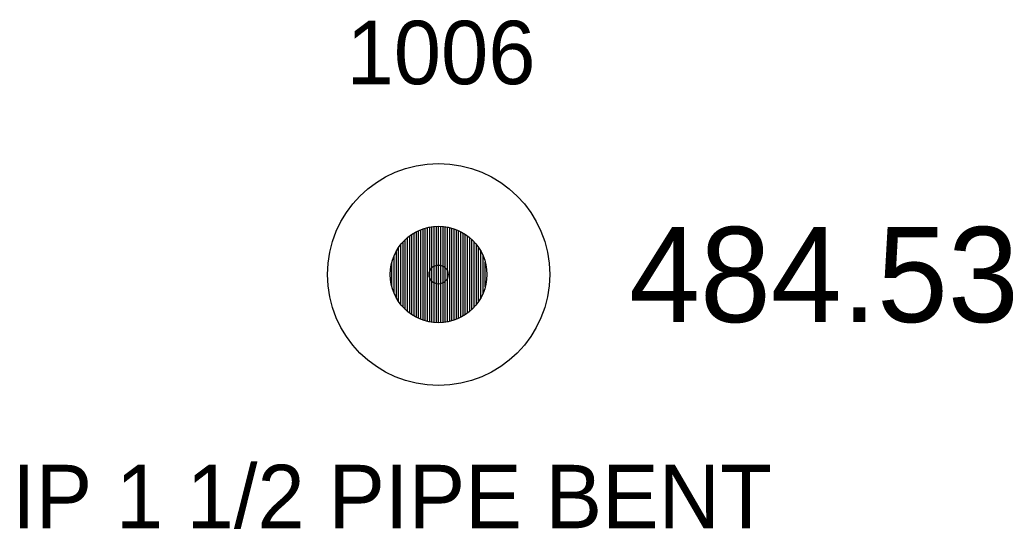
# Model space of a CAD drawing. Extents: x 1796360 to 1799195, y 895805 to 899730.
# Drawn here: x 1799179.36 to 1799195, y 899593.12 to 899601.15 of the extents above; entities that cross this region are included whole.
import ezdxf

# ---------------------------------------------------------------- set-up
doc = ezdxf.new("R2010")
doc.units = 0
for name, color, linetype in [('RD_EX_DV_Prop_txCode', 7, 'Continuous'), ('RD_EX_DV_PropPin', 7, 'Continuous'), ('RD_EX_TX_DV_Prop_ELEV', 7, 'Continuous'), ('RD_SMD_Locator', 7, 'Continuous')]:
    doc.layers.add(name, color=color, linetype=linetype)

msp = doc.modelspace()

# ---------------------------------------------------------------- linework, layer by layer
at = {"layer": 'RD_EX_DV_PropPin'}
for p, q in [((1799185.745, 899596.4), (1799185.745, 899597.863)), ((1799185.78, 899596.391), (1799185.78, 899597.873)), ((1799185.815, 899596.384), (1799185.815, 899597.88)), ((1799185.85, 899596.378), (1799185.85, 899597.886)), ((1799185.885, 899596.374), (1799185.885, 899597.89)), ((1799185.92, 899596.372), (1799185.92, 899597.892)), ((1799185.955, 899596.371), (1799185.955, 899597.893)), ((1799185.99, 899596.372), (1799185.99, 899597.892)), ((1799186.025, 899596.374), (1799186.025, 899597.89)), ((1799186.06, 899596.378), (1799186.06, 899597.886)), ((1799186.095, 899596.384), (1799186.095, 899597.88)), ((1799186.13, 899596.391), (1799186.13, 899597.873)), ((1799186.165, 899596.4), (1799186.165, 899597.863)), ((1799185.465, 899596.55), (1799185.465, 899597.714)), ((1799185.5, 899596.522), (1799185.5, 899597.742)), ((1799185.535, 899596.497), (1799185.535, 899597.766)), ((1799185.57, 899596.476), (1799185.57, 899597.788)), ((1799185.605, 899596.456), (1799185.605, 899597.808)), ((1799185.64, 899596.439), (1799185.64, 899597.825)), ((1799185.675, 899596.424), (1799185.675, 899597.839)), ((1799185.71, 899596.411), (1799185.71, 899597.852)), ((1799186.2, 899596.411), (1799186.2, 899597.852)), ((1799186.235, 899596.424), (1799186.235, 899597.839)), ((1799186.27, 899596.439), (1799186.27, 899597.825)), ((1799186.305, 899596.456), (1799186.305, 899597.808)), ((1799186.34, 899596.476), (1799186.34, 899597.788)), ((1799186.375, 899596.497), (1799186.375, 899597.766)), ((1799186.41, 899596.522), (1799186.41, 899597.742)), ((1799186.445, 899596.55), (1799186.445, 899597.714)), ((1799185.325, 899596.705), (1799185.325, 899597.558)), ((1799185.36, 899596.658), (1799185.36, 899597.606)), ((1799185.395, 899596.617), (1799185.395, 899597.647)), ((1799185.43, 899596.581), (1799185.43, 899597.683)), ((1799186.48, 899596.581), (1799186.48, 899597.683)), ((1799186.515, 899596.617), (1799186.515, 899597.647)), ((1799186.55, 899596.658), (1799186.55, 899597.606)), ((1799186.585, 899596.705), (1799186.585, 899597.558)), ((1799185.255, 899596.834), (1799185.255, 899597.43)), ((1799185.29, 899596.762), (1799185.29, 899597.501)), ((1799186.62, 899596.762), (1799186.62, 899597.501)), ((1799186.655, 899596.834), (1799186.655, 899597.43)), ((1799185.22, 899596.936), (1799185.22, 899597.328)), ((1799186.69, 899596.936), (1799186.69, 899597.328))]:
    msp.add_line(p, q, dxfattribs=at)
for radius in [1.75, 0.761]:
    msp.add_circle((1799185.955, 899597.132), radius, dxfattribs=at)
at = {"layer": 'RD_SMD_Locator'}
msp.add_circle((1799185.955, 899597.132), 0.15, dxfattribs=at)

# ---------------------------------------------------------------- texts
at = {"layer": 'RD_EX_DV_Prop_txCode'}
for s, p in [('1006', (1799184.506, 899600.132)), ('IP 1 1/2 PIPE BENT', (1799179.238, 899593.132))]:
    msp.add_text(s, height=1, dxfattribs=at).set_placement(p)
at = {"layer": 'RD_EX_TX_DV_Prop_ELEV'}
msp.add_text('484.53', height=1.5, dxfattribs=at).set_placement((1799188.955, 899596.382))

doc.saveas('drawing.dxf')
